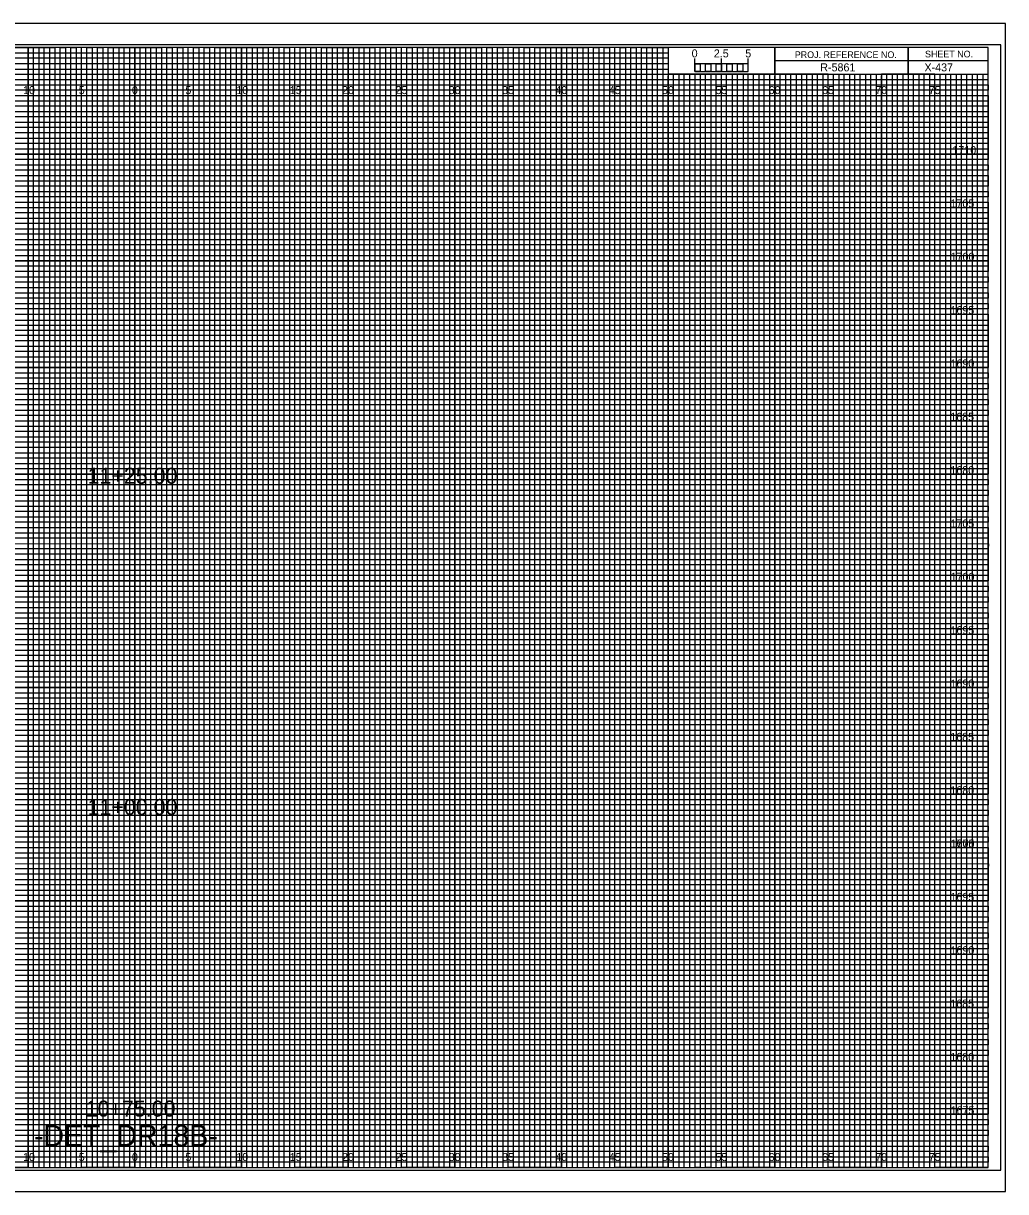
# Model space of a CAD drawing. Extents: x -7 to 162, y -2 to 217.
# Drawn here: x 69.5 to 161.7, y 107.7 to 217.2 of the extents above; entities that cross this region are included whole.
import ezdxf

# ---------------------------------------------------------------- set-up
doc = ezdxf.new("R2010")
doc.units = 0
for name, color, linetype in [('Prop Horizontal Alignment', 7, 'Continuous'), ('Prop XS Alignment Label', 7, 'Continuous'), ('Prop XS Bar Scale Labels', 7, 'Continuous'), ('Prop XS Project Number', 7, 'Continuous'), ('Prop XS Sheet Number', 7, 'Continuous'), ('Raster_Level_0', 7, 'Continuous'), ('Scratch_Level_3', 7, 'Continuous'), ('Sheet Cross Section CELL', 7, 'Continuous'), ('Sheet Cross Section Grid Major CELL', 7, 'Continuous'), ('Sheet Cross Section Grid Middle CELL', 7, 'Continuous'), ('Sheet Cross Section Grid Minor 1 CELL', 7, 'Continuous'), ('Sheet Cross Section Grid Minor 2 CELL', 7, 'Continuous'), ('Sheet Cross Section Scale CELL', 7, 'Continuous'), ('Sheet Cutting Line CELL', 7, 'Continuous'), ('Sheet DOT Grid CELL', 7, 'Continuous'), ('Sheet Plot Border Inside CELL', 7, 'Continuous'), ('Sheet Plot Border Outside CELL', 7, 'Continuous')]:
    doc.layers.add(name, color=color, linetype=linetype)

msp = doc.modelspace()

# ---------------------------------------------------------------- linework, layer by layer
at = {"layer": 'Sheet Cross Section CELL'}
for p, q in [((152.5, 215), (152.5, 212.5)), ((152.5, 212.5), (152.5, 215)), ((160, 213.75), (140, 213.75)), ((140, 213.75), (140, 212.5)), ((140, 212.5), (160, 212.5))]:
    msp.add_line(p, q, dxfattribs=at)
for points in [[(160, 215), (0, 215), (0, 110), (160, 110)], [(140, 215), (130, 215), (130, 212.52), (140, 212.52)], [(160, 215), (140, 215), (140, 212.5), (160, 212.5)]]:
    msp.add_lwpolyline(points, close=True, dxfattribs=at)
at = {"layer": 'Sheet Cross Section Grid Major CELL'}
for p, q in [((75, 215), (70, 215)), ((70, 215), (70, 110)), ((75, 110), (75, 215)), ((85, 215), (80, 215)), ((80, 215), (80, 110)), ((85, 110), (85, 215)), ((95, 215), (90, 215)), ((90, 215), (90, 110)), ((95, 110), (95, 215)), ((105, 215), (100, 215)), ((100, 215), (100, 110)), ((105, 110), (105, 215)), ((115, 215), (110, 215)), ((110, 215), (110, 110)), ((115, 110), (115, 215)), ((125, 215), (120, 215)), ((120, 215), (120, 110)), ((125, 110), (125, 215)), ((130, 215), (130, 110)), ((135, 110), (135, 212.5)), ((145, 212.5), (140, 212.5)), ((140, 212.5), (140, 110)), ((145, 110), (145, 212.5)), ((155, 212.5), (150, 212.5)), ((150, 212.5), (150, 110)), ((155, 110), (155, 212.5)), ((70, 110), (65, 110)), ((80, 110), (75, 110)), ((90, 110), (85, 110)), ((100, 110), (95, 110)), ((110, 110), (105, 110)), ((120, 110), (115, 110)), ((130, 110), (125, 110)), ((140, 110), (135, 110)), ((150, 110), (145, 110)), ((160, 110), (155, 110)), ((160, 110), (160, 110))]:
    msp.add_line(p, q, dxfattribs=at)
for points in [[(0, 210), (160, 210), (160, 205), (0, 205)], [(0, 200), (160, 200), (160, 195), (0, 195)], [(0, 190), (160, 190), (160, 185), (0, 185)], [(0, 180), (160, 180), (160, 175), (0, 175)], [(0, 170), (160, 170), (160, 165), (0, 165)], [(0, 160), (160, 160), (160, 155), (0, 155)], [(0, 150), (160, 150), (160, 145), (0, 145)], [(0, 140), (160, 140), (160, 135), (0, 135)], [(0, 130), (160, 130), (160, 125), (0, 125)], [(0, 120), (160, 120), (160, 115), (0, 115)]]:
    msp.add_lwpolyline(points, dxfattribs=at)
at = {"layer": 'Sheet Cross Section Grid Middle CELL'}
for points in [[(67.5, 215), (72.5, 215), (72.5, 110), (77.5, 110), (77.5, 215), (82.5, 215), (82.5, 110), (87.5, 110), (87.5, 215), (92.5, 215), (92.5, 110), (97.5, 110), (97.5, 215), (102.5, 215), (102.5, 110), (107.5, 110), (107.5, 215), (112.5, 215), (112.5, 110), (117.5, 110), (117.5, 215), (122.5, 215), (122.5, 110), (127.5, 110), (127.5, 215), (129.97, 215), (130, 215), (130, 212.5), (132.5, 212.5), (132.5, 110), (137.5, 110), (137.5, 212.5), (142.5, 212.5), (142.5, 110), (147.5, 110), (147.5, 212.5), (152.5, 212.5), (152.5, 110), (157.5, 110), (157.5, 212.5)], [(0, 212.5), (137.5, 212.5)], [(0, 202.5), (160, 202.5), (160, 207.5), (0, 207.5)], [(0, 192.5), (160, 192.5), (160, 197.5), (0, 197.5)], [(0, 182.5), (160, 182.5), (160, 187.5), (0, 187.5)], [(0, 172.5), (160, 172.5), (160, 177.5), (0, 177.5)], [(0, 162.5), (160, 162.5), (160, 167.5), (0, 167.5)], [(0, 152.5), (160, 152.5), (160, 157.5), (0, 157.5)], [(0, 142.5), (160, 142.5), (160, 147.5), (0, 147.5)], [(0, 132.5), (160, 132.5), (160, 137.5), (0, 137.5)], [(0, 122.5), (160, 122.5), (160, 127.5), (0, 127.5)], [(0, 112.5), (160, 112.5), (160, 117.5), (0, 117.5)]]:
    msp.add_lwpolyline(points, dxfattribs=at)
at = {"layer": 'Sheet Cross Section Grid Minor 1 CELL'}
for p, q in [((0, 214.5), (130, 214.5)), ((130, 213.99), (0, 213.99)), ((130, 214.5), (130, 213.99)), ((0, 213.5), (130, 213.5)), ((130, 212.94), (0, 212.94)), ((130, 213.5), (130, 212.94)), ((0, 212), (160, 212))]:
    msp.add_line(p, q, dxfattribs=at)
for points in [[(0, 211.5), (135, 211.5), (160, 211.5), (160, 211), (0, 211)], [(0, 210.5), (160, 210.5), (160, 209.5), (0, 209.5)], [(0, 209), (160, 209), (160, 208.5), (0, 208.49)], [(0, 208), (160, 208), (160, 207), (0, 207)], [(0, 206.5), (160, 206.5), (160, 206), (0, 206)], [(0, 205.5), (160, 205.5), (160, 204.5), (0, 204.5)], [(0, 204), (160, 204), (160, 203.5), (0, 203.5)], [(0, 203), (160, 203), (160, 202), (0, 202)], [(0, 201.5), (160, 201.5), (160, 201), (0, 201)], [(0, 200.5), (160, 200.5), (160, 199.5), (0, 199.5)], [(0, 199), (160, 199), (160, 198.5), (0, 198.5)], [(0, 198), (160, 198), (160, 196.97), (160, 196.5), (160, 196), (0, 196)], [(0, 197), (160, 197), (160, 196.5), (0, 196.5)], [(0, 195.5), (160, 195.5), (160, 194.5), (0, 194.52)], [(0, 194.52), (160, 194.5), (160, 194), (0, 194)], [(0, 193.5), (160, 193.5), (160, 193), (0, 193)], [(0, 192), (160, 192), (160, 191.5), (0, 191.5)], [(0, 191), (160, 191), (160, 190.5), (0, 190.5)], [(-0.04, 189.44), (160, 189.44), (160, 188.94), (-0.04, 188.94)], [(0, 188.5), (160, 188.5), (160, 188), (0, 188)], [(0, 187), (160, 187), (160, 186.5), (0, 186.5)], [(0, 186), (160, 186), (160, 185.5), (0, 185.5)], [(0, 184.5), (160, 184.5), (160, 184), (0, 184)], [(0, 183.5), (160, 183.5), (160, 183), (0, 183)], [(0, 182), (160, 182), (160, 181.5), (0, 181.5)], [(0, 181), (160, 181), (160, 180.5), (0, 180.5)], [(0, 179.5), (160, 179.5), (160, 178.99), (0, 179)], [(0, 178.5), (160, 178.5), (160, 178), (0, 178)], [(0, 177), (160, 177), (160, 176.5), (0, 176.5)], [(0, 176), (160, 176), (160, 175.5), (0, 175.5)], [(0, 174.5), (160, 174.5), (160, 174), (0, 174)], [(0, 173.5), (160, 173.5), (160, 173), (0, 173)], [(0, 172), (160, 172), (160, 171.5), (0, 171.5)], [(0, 171), (160, 171), (160, 170.5), (0, 170.5)], [(0, 169.5), (160, 169.5), (160, 169), (0, 169)], [(0, 168.5), (160.03, 168.46), (160, 168), (0, 168)], [(0, 167), (160, 167), (160, 166.5), (0, 166.5)], [(0, 166), (160, 166), (160, 165.5), (0, 165.5)], [(0, 164.5), (160, 164.5), (160, 164), (0, 164)], [(0, 163.5), (160, 163.5), (160, 163), (0, 163)], [(0, 162), (160, 162), (160, 161.5), (0, 161.5)], [(0, 161), (160, 161), (160, 160.5), (0, 160.5)], [(0, 159.5), (160, 159.5), (160, 159), (0, 159)], [(0, 158.5), (160, 158.5), (160, 158), (0, 158)], [(0, 157), (160, 157), (160, 156.5), (0, 156.5)], [(0, 156), (160, 156), (160, 155.5), (0, 155.5)], [(0, 154.5), (160, 154.5), (160, 154), (0, 154)], [(0, 153.5), (160, 153.5), (160, 153), (0, 153)], [(0, 152), (160, 152), (160, 151.5), (0, 151.5)], [(0, 151), (160, 151), (160, 150.5), (0, 150.5)], [(0, 149.5), (160, 149.5), (160, 148.99), (0, 149)], [(0, 148.5), (160, 148.5), (160, 148), (0, 148)], [(0, 147), (160, 147), (160, 146.5), (0, 146.5)], [(0, 146), (160, 146), (160, 145.5), (0, 145.5)], [(0, 144.5), (160, 144.5), (160, 144), (0, 144)], [(0, 143.5), (160, 143.5), (160, 143), (0, 143)], [(0, 142), (160, 142), (160, 141.5), (0, 141.5)], [(0, 141), (160, 141), (160, 140.5), (0, 140.5)], [(0, 139.5), (160, 139.5), (160, 139), (0, 139)], [(0, 138.5), (160.03, 138.46), (160, 138), (0, 138)], [(0, 137), (160, 137), (160, 136.5), (0, 136.5)], [(0, 136), (160, 136), (160, 135.5), (0, 135.5)], [(0, 134.5), (160, 134.5), (160, 134), (0, 134)], [(0, 133.5), (160, 133.5), (160, 133), (0, 133)], [(0, 132), (160, 132), (160, 131.5), (0, 131.5)], [(0, 131), (160, 131), (160, 130.5), (0, 130.5)], [(0, 129.5), (160, 129.5), (160, 129), (0, 129)], [(0, 128.5), (160, 128.5), (160, 128), (0, 128)], [(0, 127), (160, 127), (160, 126.5), (0, 126.5)], [(0, 126), (160, 126), (160, 125.5), (0, 125.5)], [(0, 124.5), (160, 124.5), (160, 124), (0, 124)], [(0, 123.5), (160, 123.5), (160, 123), (0, 123)], [(0, 122), (160, 122), (160, 121.5), (0, 121.5)], [(0, 121), (160, 121), (160, 120.5), (0, 120.5)], [(0, 119.5), (160, 119.5), (160, 119), (0, 119)], [(0, 118.5), (160, 118.5), (160, 118), (0, 118)], [(0, 117), (160, 117), (160, 116.5), (0, 116.5)], [(0, 116), (160, 116), (160, 115.5), (0, 115.5)], [(0, 114.5), (160, 114.5), (160, 114), (0, 114)], [(0, 113.5), (160, 113.5), (160, 113), (0, 113)], [(0, 112), (160, 112), (160, 111.5), (0, 111.5)], [(0, 111), (160, 111), (160, 110.5), (0, 110.5)]]:
    msp.add_lwpolyline(points, dxfattribs=at)
at = {"layer": 'Sheet Cross Section Grid Minor 2 CELL'}
for p, q in [((133.5, 212.5), (133, 212.5)), ((133, 212.5), (133, 110)), ((133.5, 110), (133.5, 212.5)), ((134.5, 212.5), (134, 212.5)), ((134, 212.5), (134, 110)), ((134.5, 110), (134.5, 212.5)), ((133, 110), (132.5, 110)), ((134, 110), (133.5, 110))]:
    msp.add_line(p, q, dxfattribs=at)
for points in [[(70, 110), (70.5, 110), (70.5, 215), (71, 215), (71, 110)], [(71, 110), (71.5, 110), (71.5, 215), (72, 215), (72, 110)], [(72.5, 110), (73, 110), (73, 215), (73.5, 215), (73.5, 110)], [(73.5, 110), (74, 110), (74, 215), (74.5, 215), (74.5, 110)], [(75, 110), (75.5, 110), (75.5, 215), (76, 215), (76, 110)], [(76, 110), (76.5, 110), (76.5, 215), (77, 215), (77, 110)], [(77.5, 110), (78, 110), (78, 215), (78.5, 215), (78.5, 110)], [(78.5, 110), (79, 110), (79, 215), (79.5, 215), (79.5, 110)], [(80, 110), (80.5, 110), (80.5, 215), (81, 215), (81, 110)], [(81, 110), (81.5, 110), (81.5, 215), (82, 215), (82, 110)], [(82.5, 110), (83, 110), (83, 215), (83.5, 215), (83.5, 110)], [(83.5, 110), (84, 110), (84, 215), (84.5, 215), (84.5, 110)], [(85, 110), (85.5, 110), (85.5, 215), (86, 215), (86, 110)], [(86, 110), (86.5, 110), (86.5, 215), (87, 215), (87, 110)], [(87.5, 110), (88, 110), (88, 215), (88.5, 215), (88.5, 110)], [(88.5, 110), (89, 110), (89, 215), (89.5, 215), (89.5, 110)], [(90, 110), (90.5, 110), (90.5, 215), (91, 215), (91, 110)], [(91, 110), (91.5, 110), (91.5, 215), (92, 215), (92, 110)], [(92.5, 110), (93, 110), (93, 215), (93.5, 215), (93.5, 110)], [(93.5, 110), (94, 110), (94, 215), (94.5, 215), (94.5, 110)], [(95, 110), (95.5, 110), (95.5, 215), (96, 215), (96, 110)], [(96, 110), (96.5, 110), (96.5, 215), (97, 215), (97, 110)], [(97.5, 110), (98, 110), (98, 215), (98.5, 215), (98.5, 110)], [(98.5, 110), (99, 110), (99, 215), (99.5, 215), (99.5, 110)], [(100, 110), (100.5, 110), (100.5, 215), (101, 215), (101, 110)], [(101, 110), (101.5, 110), (101.5, 215), (102, 215), (102, 110)], [(102.5, 110), (103, 110), (103, 215), (103.5, 215), (103.5, 110)], [(103.5, 110), (104, 110), (104, 215), (104.5, 215), (104.5, 110)], [(105, 110), (105.5, 110), (105.5, 215), (106, 215), (106, 110)], [(106, 110), (106.5, 110), (106.5, 215), (107, 215), (107, 110)], [(107.5, 110), (108, 110), (108, 215), (108.5, 215), (108.5, 110)], [(108.5, 110), (109, 110), (109, 215), (109.5, 215), (109.5, 110)], [(110, 110), (110.5, 110), (110.5, 215), (111, 215), (111, 110)], [(111, 110), (111.5, 110), (111.5, 215), (112, 215), (112, 110)], [(112.5, 110), (113, 110), (113, 215), (113.5, 215), (113.5, 110)], [(113.5, 110), (114, 110), (114, 215), (114.5, 215), (114.5, 110)], [(115, 110), (115.5, 110), (115.5, 215), (116, 215), (116, 110)], [(116, 110), (116.5, 110), (116.5, 215), (117, 215), (117, 110)], [(117.5, 110), (118, 110), (118, 215), (118.5, 215), (118.5, 110)], [(118.5, 110), (119, 110), (119, 215), (119.5, 215), (119.5, 110)], [(120, 110), (120.5, 110), (120.5, 215), (121, 215), (121, 110)], [(121, 110), (121.5, 110), (121.5, 215), (122, 215), (122, 110)], [(122.5, 110), (123, 110), (123, 215), (123.5, 215), (123.5, 110)], [(123.5, 110), (124, 110), (124, 215), (124.5, 215), (124.5, 110)], [(125, 110), (125.5, 110), (125.5, 215), (126, 215), (126, 110)], [(126, 110), (126.5, 110), (126.5, 215), (127, 215), (127, 110)], [(127.5, 110), (128, 110), (128, 215), (128.5, 215), (128.5, 110)], [(128.5, 110), (129, 110), (129, 215), (129.5, 215), (129.5, 110)], [(130, 110), (130.5, 110), (130.5, 212.5), (131.01, 212.5), (131.01, 110)], [(131, 110), (131.5, 110), (131.5, 212.5), (132, 212.5), (132, 110)], [(135, 110), (135.49, 110), (135.49, 212.5), (136, 212.5), (136, 110)], [(136, 110), (136.5, 110), (136.5, 212.5), (137.03, 212.5), (137.03, 110)], [(137.5, 110), (138, 110), (138, 212.5), (138.5, 212.5), (138.5, 110)], [(138.5, 110), (139, 110), (139, 212.5), (139.5, 212.5), (139.5, 110)], [(140, 110), (140.5, 110), (140.5, 212.5), (141, 212.5), (141, 110)], [(141, 110), (141.5, 110), (141.5, 212.5), (142, 212.5), (142, 110)], [(142.5, 110), (143, 110), (143, 212.5), (143.5, 212.5), (143.5, 110)], [(143.5, 110), (144, 110), (144, 212.5), (144.5, 212.5), (144.5, 110)], [(145, 110), (145.5, 110), (145.5, 212.5), (146, 212.5), (146, 110)], [(146, 110), (146.5, 110), (146.5, 212.5), (147, 212.5), (147, 110)], [(147.5, 110), (148, 110), (148, 212.5), (148.5, 212.5), (148.5, 110)], [(148.5, 110), (149, 110), (149, 212.5), (149.5, 212.5), (149.5, 110)], [(150, 110), (150.5, 110), (150.5, 212.5), (151, 212.5), (151, 110)], [(151, 110), (151.5, 110), (151.5, 212.5), (152, 212.5), (152, 110)], [(152.5, 110), (153, 110), (153, 212.5), (153.5, 212.5), (153.5, 110)], [(153.5, 110), (154, 110), (154, 212.5), (154.5, 212.5), (154.5, 110)], [(155, 110), (155.5, 110), (155.5, 212.5), (156, 212.5), (156, 110)], [(156, 110), (156.5, 110), (156.5, 212.5), (157, 212.5), (157, 110)], [(157.5, 110), (158, 110), (158, 212.5), (158.5, 212.5), (158.5, 110)], [(158.5, 110), (159, 110), (159, 212.5), (159.5, 212.5), (159.5, 110)]]:
    msp.add_lwpolyline(points, dxfattribs=at)
at = {"layer": 'Sheet Cross Section Scale CELL'}
for p, q in [((132.5, 212.75), (132.5, 213.95)), ((132.5, 213.45), (132.5, 213.95)), ((135, 212.75), (135, 213.95)), ((137.5, 212.75), (137.5, 213.95)), ((137.5, 213.45), (137.5, 213.95))]:
    msp.add_line(p, q, dxfattribs=at)
for points in [[(137.5, 213.45), (132.5, 213.45), (132.5, 212.75), (137.5, 212.75)], [(132.5, 213.45), (133, 213.45), (133, 212.75), (132.5, 212.75)], [(133.5, 213.45), (134, 213.45), (134, 212.75), (133.5, 212.75)], [(134.5, 213.45), (135, 213.45), (135, 212.75), (134.5, 212.75)], [(135.5, 213.45), (136, 213.45), (136, 212.75), (135.5, 212.75)], [(136.5, 213.45), (137, 213.45), (137, 212.75), (136.5, 212.75)]]:
    msp.add_lwpolyline(points, close=True, dxfattribs=at)
at = {"layer": 'Sheet Cutting Line CELL'}
for p, q in [((161.65, 217.25), (-6.7, 217.25)), ((-6.7, 107.75), (161.65, 107.75))]:
    msp.add_line(p, q, dxfattribs=at)
at = {"layer": 'Sheet DOT Grid CELL'}
for p, q in [((70, 110), (70, 215)), ((75, 110), (75, 215)), ((80, 110), (80, 215)), ((85, 110), (85, 215)), ((90, 110), (90, 215)), ((95, 110), (95, 215)), ((100, 110), (100, 215)), ((105, 110), (105, 215)), ((110, 110), (110, 215)), ((115, 110), (115, 215)), ((120, 110), (120, 215)), ((125, 110), (125, 215)), ((130, 110), (130, 212.34)), ((135, 110), (135, 212.34)), ((140, 110), (140, 212.34)), ((145, 110), (145, 212.34)), ((150, 110), (150, 212.34)), ((155, 110), (155, 212.34)), ((0, 210), (160, 210)), ((0, 205), (160, 205)), ((0, 200), (160, 200)), ((0, 195), (160, 195)), ((0, 190), (160, 190)), ((0, 185), (160, 185)), ((0, 180), (160, 180)), ((0, 175), (160, 175)), ((0, 170), (160, 170)), ((0, 165), (160, 165)), ((0, 160), (160, 160)), ((0, 155), (160, 155)), ((0, 150), (160, 150)), ((0, 145), (160, 145)), ((0, 140), (160, 140)), ((0, 135), (160, 135)), ((0, 130), (160, 130)), ((0, 125), (160, 125)), ((0, 120), (160, 120)), ((0, 115), (160, 115))]:
    msp.add_line(p, q, dxfattribs=at)
at = {"layer": 'Sheet Plot Border Inside CELL'}
msp.add_lwpolyline([(-5.4, 109.75), (161.2, 109.75), (161.2, 215.25), (-5.4, 215.25)], close=True, dxfattribs=at)
at = {"layer": 'Sheet Plot Border Outside CELL'}
msp.add_lwpolyline([(-6.7, 107.75), (161.65, 107.75), (161.65, 217.25), (-6.7, 217.25)], close=True, dxfattribs=at)

# ---------------------------------------------------------------- texts
at = {"layer": 'Prop Horizontal Alignment'}
for s, p in [('11+25.00', (75.57, 174.1)), ('11+00.00', (75.57, 143.05)), ('10+75.00', (75.39, 114.78))]:
    msp.add_text(s, height=1.5, dxfattribs=at).set_placement(p)
at = {"layer": 'Prop XS Alignment Label'}
msp.add_text('-DET_DR18B-', height=2, dxfattribs=at).set_placement((70.54, 112))
at = {"layer": 'Prop XS Bar Scale Labels'}
for s, p in [('2.5', (134.29, 214.06)), ('5', (137.24, 214.06))]:
    msp.add_text(s, height=0.75, dxfattribs=at).set_placement(p)
at = {"layer": 'Prop XS Project Number'}
msp.add_text('R-5861', height=0.75, dxfattribs=at).set_placement((144.27, 212.75))
at = {"layer": 'Prop XS Sheet Number'}
msp.add_text('X-437', height=0.75, dxfattribs=at).set_placement((154.04, 212.75))
at = {"layer": 'Raster_Level_0'}
for s, p in [('10', (69.52, 210.62)), ('5', (74.74, 210.62)), ('0', (79.73, 210.62)), ('0', (79.73, 210.62)), ('5', (84.74, 210.62)), ('10', (89.52, 210.62)), ('15', (94.53, 210.62)), ('20', (99.43, 210.62)), ('25', (104.44, 210.62)), ('30', (109.43, 210.62)), ('35', (114.44, 210.62)), ('40', (119.43, 210.62)), ('45', (124.44, 210.62)), ('50', (129.43, 210.62)), ('55', (134.44, 210.62)), ('60', (139.43, 210.62)), ('65', (144.44, 210.62)), ('70', (149.43, 210.62)), ('75', (154.44, 210.62)), ('10', (69.52, 110.62)), ('5', (74.74, 110.62)), ('0', (79.73, 110.62)), ('0', (79.73, 110.62)), ('5', (84.74, 110.62)), ('10', (89.52, 110.62)), ('15', (94.53, 110.62)), ('20', (99.43, 110.62)), ('25', (104.44, 110.62)), ('30', (109.43, 110.62)), ('35', (114.44, 110.62)), ('40', (119.43, 110.62)), ('45', (124.44, 110.62)), ('50', (129.43, 110.62)), ('55', (134.44, 110.62)), ('60', (139.43, 110.62)), ('65', (144.44, 110.62)), ('70', (149.43, 110.62)), ('75', (154.44, 110.62))]:
    msp.add_text(s, height=0.75, dxfattribs=at).set_placement(p)
at = {"layer": 'Scratch_Level_3'}
for s, p in [('1710', (156.66, 205)), ('1705', (156.48, 200)), ('1700', (156.49, 195)), ('1695', (156.48, 190)), ('1690', (156.48, 185)), ('1685', (156.46, 180)), ('1680', (156.47, 175)), ('1705', (156.48, 170)), ('1700', (156.49, 165)), ('1695', (156.48, 160)), ('1690', (156.48, 155)), ('1685', (156.46, 150)), ('1680', (156.47, 145)), ('1700', (156.49, 140)), ('1675', (156.49, 140)), ('1695', (156.48, 135)), ('1690', (156.48, 130)), ('1685', (156.46, 125)), ('1680', (156.47, 120)), ('1675', (156.49, 115))]:
    msp.add_text(s, height=0.75, dxfattribs=at).set_placement(p)
at = {"layer": 'Sheet Cross Section CELL'}
for s, p in [('PROJ. REFERENCE NO.', (141.88, 214)), ('SHEET NO.', (154.09, 214.06))]:
    msp.add_text(s, height=0.625, dxfattribs=at).set_placement(p)
at = {"layer": 'Sheet Cross Section Scale CELL'}
msp.add_text('0', height=0.75, dxfattribs=at).set_placement((132.21, 214.06))

doc.saveas('drawing.dxf')
